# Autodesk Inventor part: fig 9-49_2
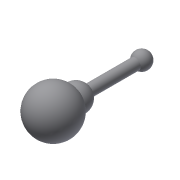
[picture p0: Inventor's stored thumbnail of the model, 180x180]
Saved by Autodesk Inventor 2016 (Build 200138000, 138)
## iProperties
Created: 2013-03
Part Number: fig 9-49_2
Material: Generic
Document SubType Name: Modeling
Designer: CADCIM
Density: 1 g/cm^3
Appearance: Default
Author: CADCIM
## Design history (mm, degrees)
sketch "Sketch1"
  geometry: L1 (0, 5)-(0, -5); A1 r 5 centre (0, 0) between (0, -5) and (0, 5); 1 further point
  constraints: 2 end point, 2 point on circle, 1 centre point, 1 coincident, 1 vertical
  dimensions: "d0" = 10 diameter of A1
revolve "Revolution1" sketch "Sketch1" stored, may be unused: angle "d2" = 90 deg
sketch "Sketch2"
  geometry: L1 (0, 20.921)-(0, 2.139); L2 (1.175, 7.426)-(1.175, 17.742); A1 r 1.807 centre (0, 19.115) between (1.175, 17.742) and (0, 20.921); A2 r 2.774 centre (0, 4.913) between (0, 2.139) and (1.175, 7.426); 1 further point
  constraints: 4 end point, 4 point on circle, 2 centre point, 1 parallel, 1 vertical
revolve "Revolution2" sketch "Sketch2" stored, may be unused: angle "d3" = 90 deg
body "Solid1"
